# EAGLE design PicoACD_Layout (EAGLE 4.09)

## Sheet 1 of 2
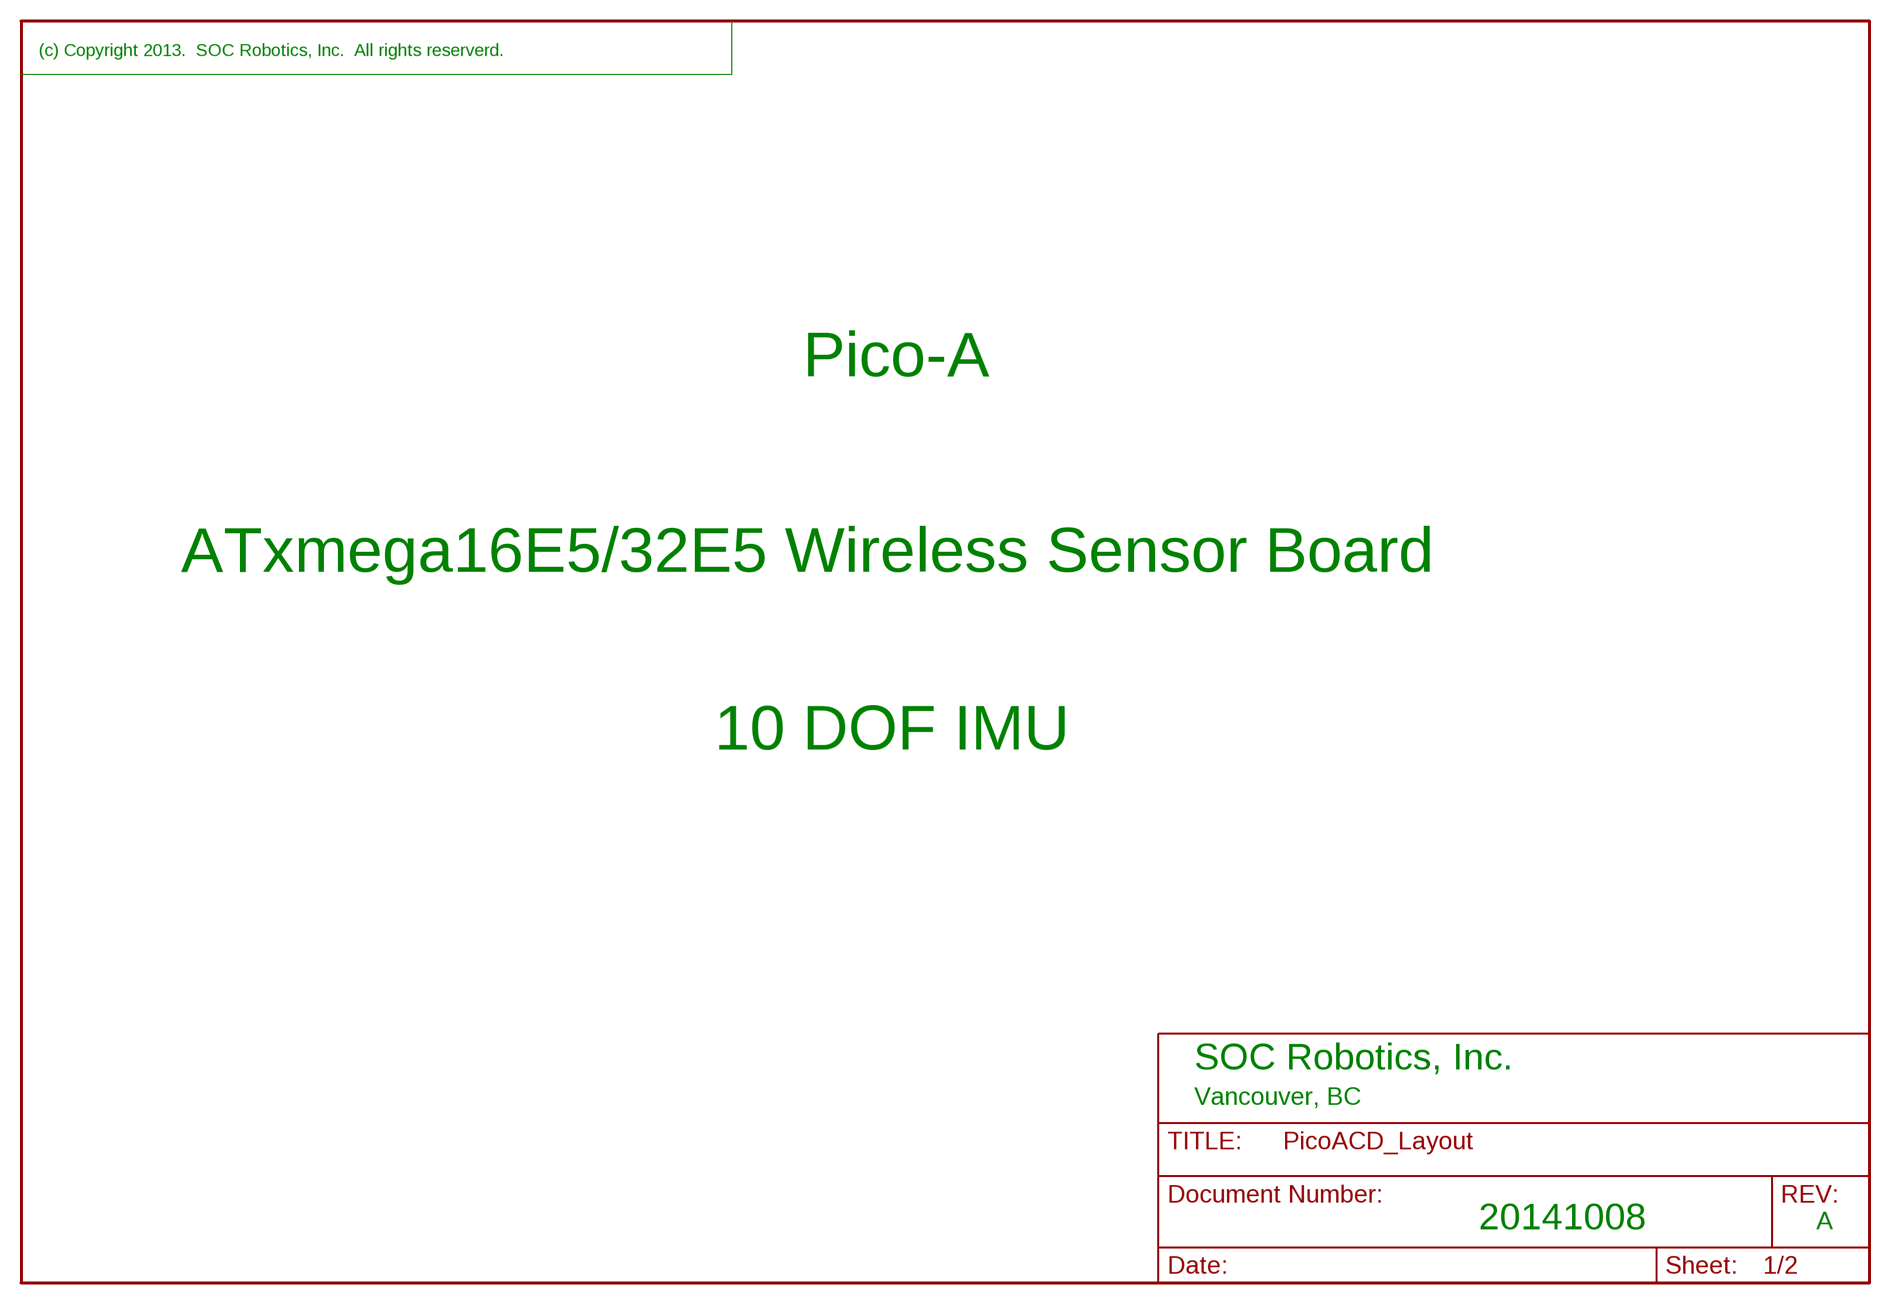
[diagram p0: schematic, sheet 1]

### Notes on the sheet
- (c) Copyright 2013.  SOC Robotics, Inc.  All rights reserverd.
- Pico-A
- ATxmega16E5/32E5 Wireless Sensor Board
- 10 DOF IMU
- SOC Robotics, Inc.
- Vancouver, BC
- 20141008 | A

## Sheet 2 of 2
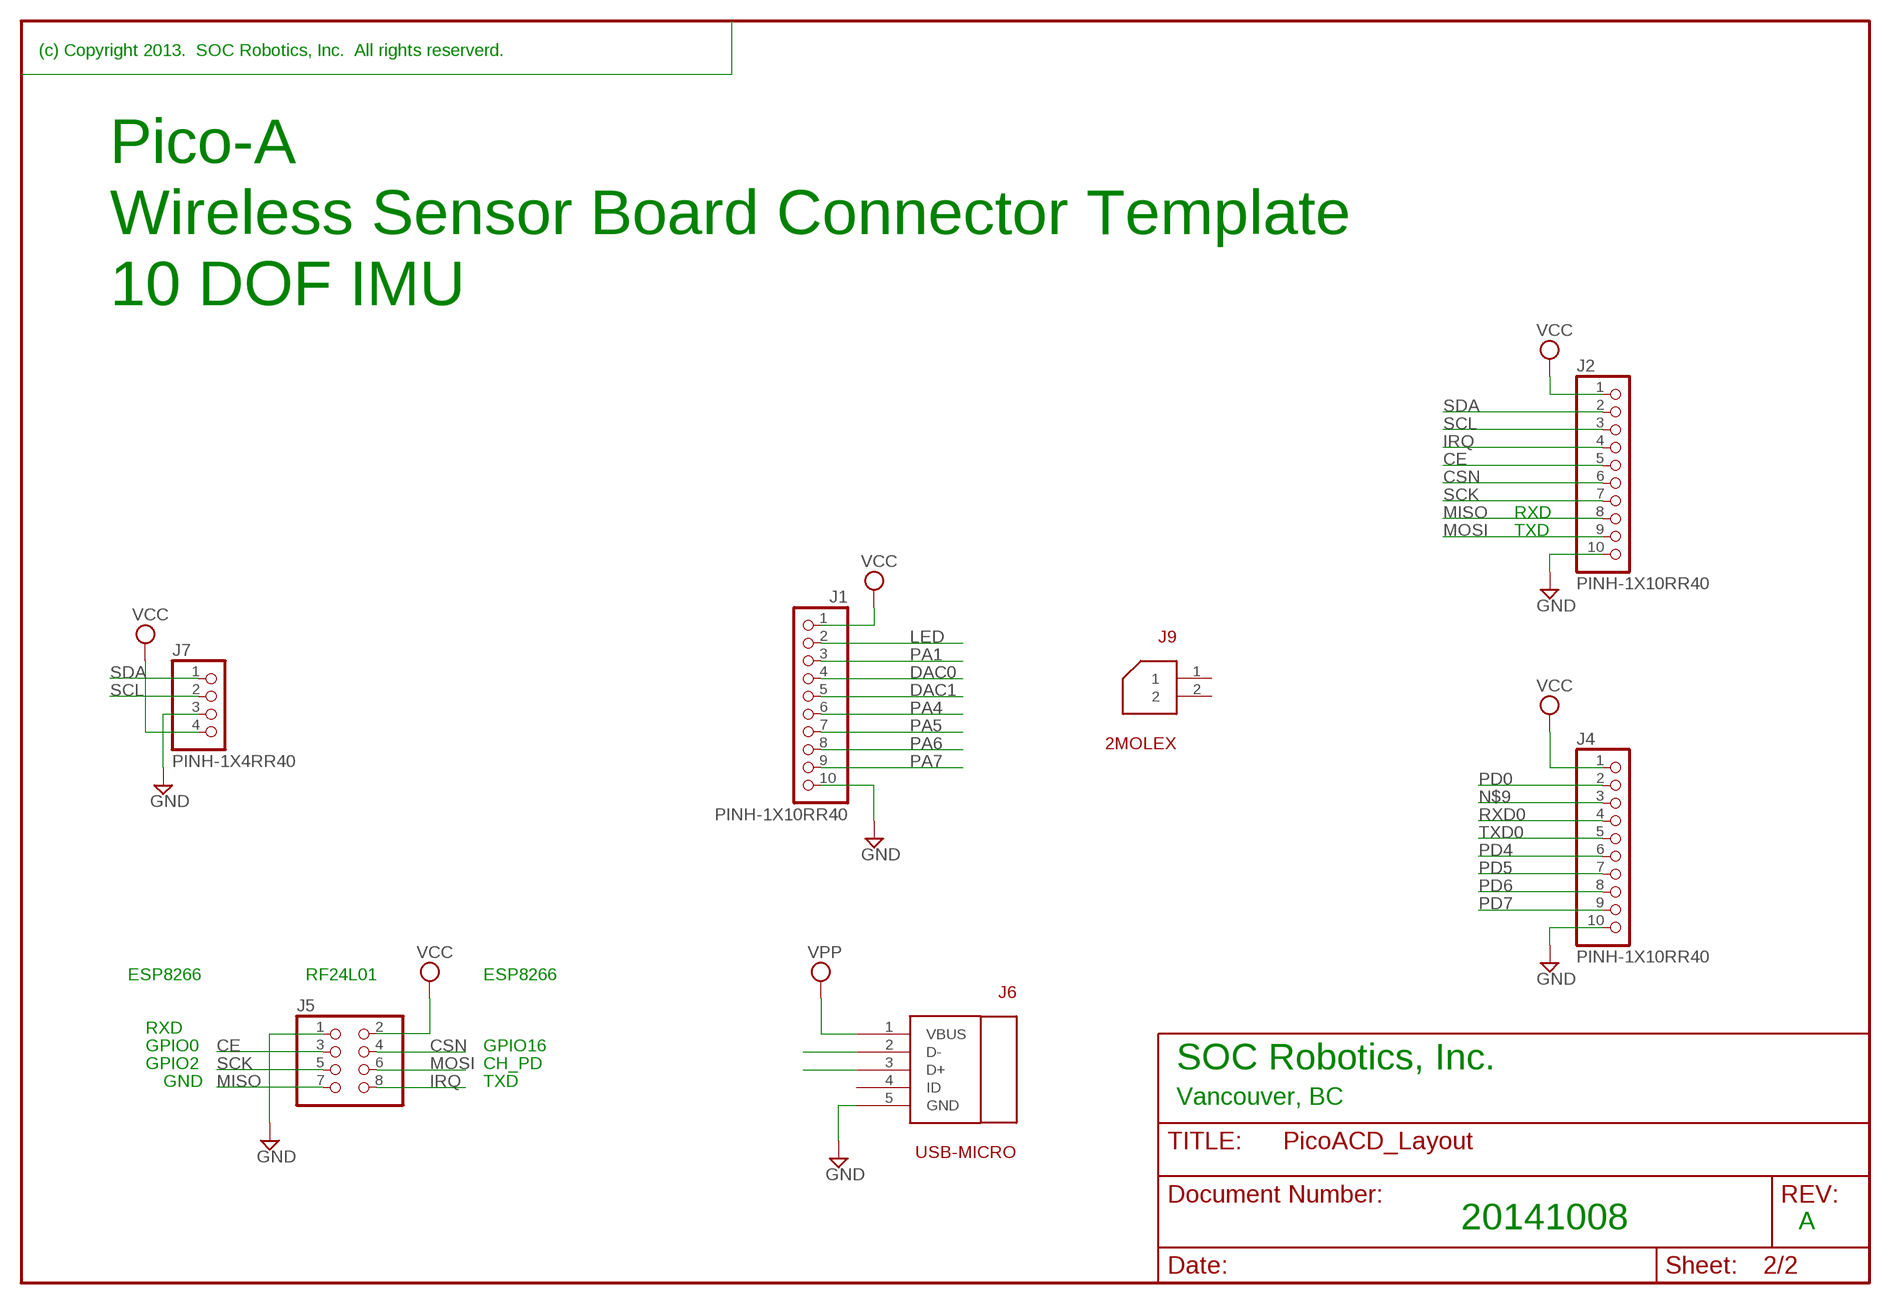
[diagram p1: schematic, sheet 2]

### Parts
J1  PINH-1X10RR40  [1X10ROUND]
J2  PINH-1X10RR40  [1X10ROUND]
J4  PINH-1X10RR40  [1X10ROUND]
J5  PINHD-2X4HEX  [2X04]
J6  USB-MICRO  [USB-MICRO]
J7  PINH-1X4RR40  [1X4ROUND]
J9  2MOLEX  PINH-1X2MOLEX  [1X2MOLEX]

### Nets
CE: J2.5 J5.3
CSN: J2.6 J5.4
DAC0: J1.4
DAC1: J1.5
GND: J1.10 J2.10 J4.10 J5.1 J6.5(GND) J7.3
IRQ: J2.4 J5.8
LED: J1.2
MISO: J2.8 J5.7
MOSI: J2.9 J5.6
N$9: J4.3
N$11: J6.2(D-)
N$12: J6.3(D+)
PA1: J1.3
PA4: J1.6
PA5: J1.7
PA6: J1.8
PA7: J1.9
PD0: J4.2
PD4: J4.6
PD5: J4.7
PD6: J4.8
PD7: J4.9
RXD0: J4.4
SCK: J2.7 J5.5
SCL: J2.3 J7.2
SDA: J2.2 J7.1
TXD0: J4.5
VCC: J1.1 J2.1 J4.1 J5.2 J7.4
VPP: J6.1(VBUS)
Unconnected: J6.4(ID) J9.1 J9.2

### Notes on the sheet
- (c) Copyright 2013.  SOC Robotics, Inc.  All rights reserverd.
- Pico-A
- Wireless Sensor Board Connector Template
- 10 DOF IMU
- RXD
- TXD
- ESP8266 | RF24L01 | ESP8266
- RXD
- GPIO0 | GPIO16
- GPIO2 | CH_PD | SOC Robotics, Inc.
- GND | TXD
- Vancouver, BC
- 20141008 | A

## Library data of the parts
J1 J2 J4 = pinhead:PINH-1X10R
J5 = pinhead:PINHD-2X4: PIN HEADER
J6 = con-TI DSK 2:USB-MICRO: Micro USB
J7 = pinhead:PINH-1X4R: 1x4 Pin Head Round
J9 = pinhead:PINH-1X2MOLEX: 1x2 Molex 1.25mm thru-hole

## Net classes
1 VCC: width 0.305 mm, drill 0.203 mm, clearance 0.432 mm
2 GND: width 0.305 mm, drill 0.203 mm, clearance 0.432 mm
3 VTARGET: width 0.305 mm, drill 0.203 mm, clearance 0.432 mm
4 VIN: width 0.305 mm, drill 0.203 mm, clearance 0.432 mm

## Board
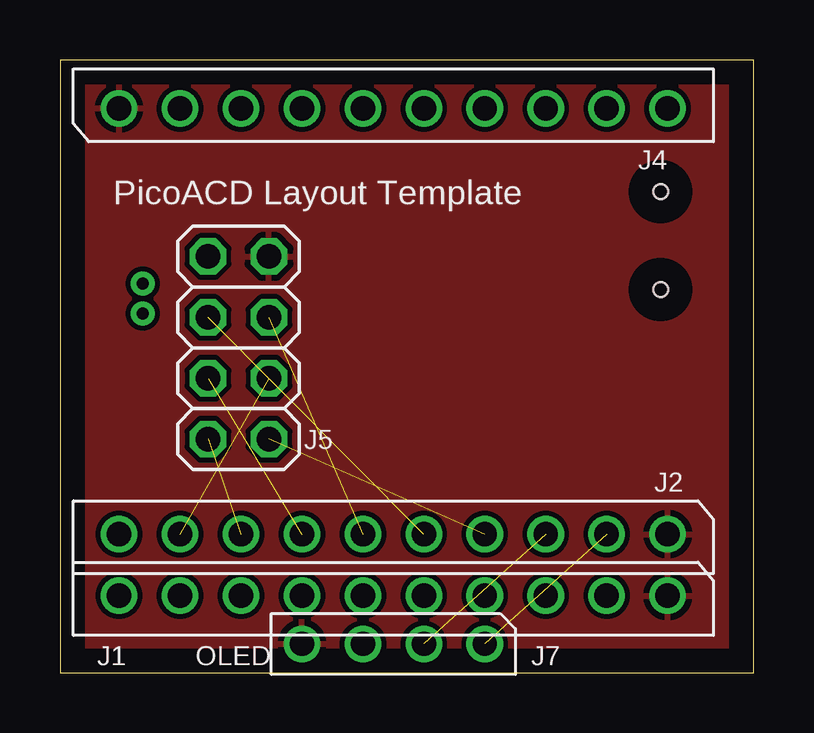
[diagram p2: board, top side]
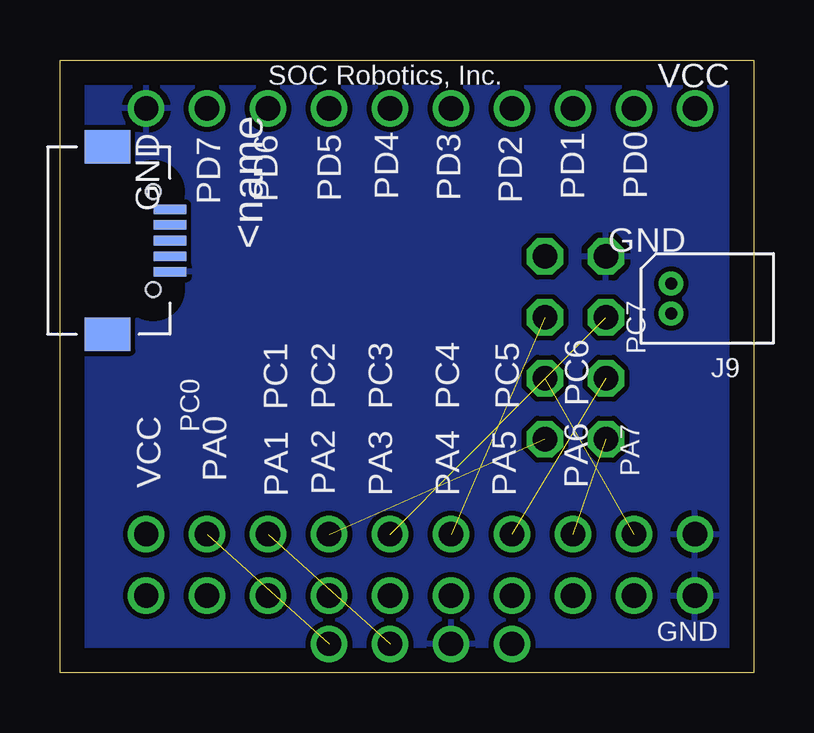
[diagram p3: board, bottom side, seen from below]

Size 28.91 x 25.55 mm. Coordinates in mm from the lower left corner, seen from the top.
Outline: 0,0 28.91,0 28.91,25.55 0,25.55 0,0
Copper layers used: Top, Bottom

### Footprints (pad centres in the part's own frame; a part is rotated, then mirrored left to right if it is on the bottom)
1X10ROUND = drill 1.016 round: 1 -11.43,0; 2 -8.89,0; 3 -6.35,0; 4 -3.81,0; 5 -1.27,0; 6 1.27,0; 7 3.81,0; 8 6.35,0; 9 8.89,0; 10 11.43,0
2X04 = drill 1.016 octagon: 1 -3.81,-1.27; 2 -3.81,1.27; 3 -1.27,-1.27; 4 -1.27,1.27; 5 1.27,-1.27; 6 1.27,1.27; 7 3.81,-1.27; 8 3.81,1.27
USB-MICRO = smd 0.4 x 1.35: 1 -1.3,0; 2 -0.65,0; 3 0,0; 4 0.65,0; 5 1.3,0 | smd 1.4 x 1.9: P$6 -3.9,-2.6; P$7 3.9,-2.6 | hole 0.61: -2.04,-0.7; 2.04,-0.7
1X4ROUND = drill 1.016 round: 1 -3.81,0; 2 -1.27,0; 3 1.27,0; 4 3.81,0
1X2MOLEX = drill 0.5 pad 0.9 round: 1 0.625,0; 2 -0.625,0

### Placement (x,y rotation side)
J1  13.89,3.21 180 top
J2  13.89,5.78 180 top
J4  13.89,23.53 0 top
J5  7.44,13.55 270 top
J6  24.33,18.02 270 bottom
J7  13.89,1.21 180 top
J9  3.45,15.61 90 bottom

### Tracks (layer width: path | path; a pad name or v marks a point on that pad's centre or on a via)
CE  (1 unrouted)
CSN  (1 unrouted)
GND
  pour Bottom: 0.1,25.44 28.8,25.44 28.8,0.11 0.1,0.11
IRQ  (1 unrouted)
MISO  (1 unrouted)
MOSI  (1 unrouted)
SCK  (1 unrouted)
SCL  (1 unrouted)
SDA  (1 unrouted)
VCC
  pour Top: 0.1,25.44 28.8,25.44 28.8,0.11 0.1,0.11

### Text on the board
tPlace: PicoACD Layout Template | OLED
bPlace: VCC | SOC Robotics, Inc. | PD0 | PD1 | PD4 | PD2 | PD3 | PD5 | PD6 | PD7 | GND | GND | PC7 | PC6 | PC5 | PC4 | PC3 | PC2 | PC1 | PC0 | PA0 | VCC | PA7 | PA6 | PA5 | PA4 | PA3 | PA2 | PA1 | GND
_tplace: L1 | R3 | C3 | R2 | C4 | J4 | C1 | C10 | U2 | LD1 | C9 | C5 | U1 | G | J3 | Pico | A | C2 | R | R6 | P | D1 | V | C7 | J5 | R4 | U5 | J1 | R5 | R1 | C6 | J2 | R10 | R11 | OLED | J7 | J8
_bplace: C11 | VCC | SOC Robotics, Inc. | PD0 | PD1 | PD2 | PD3 | PD4 | PD5 | PD6 | PD7 | GND | GND | U6 | C14 | C12 | Pico | R7 | PC7 | PC6 | PC5 | A | PC4 | PC3 | PC2 | PC1 | J9 | L2 | PC0 | R8 | C8 | PA0 | VCC | PA7 | PA6 | PA5 | PA4 | PA3 | PA2 | PA1 | R9 | U3 | U4 | J10 | GND | OLED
